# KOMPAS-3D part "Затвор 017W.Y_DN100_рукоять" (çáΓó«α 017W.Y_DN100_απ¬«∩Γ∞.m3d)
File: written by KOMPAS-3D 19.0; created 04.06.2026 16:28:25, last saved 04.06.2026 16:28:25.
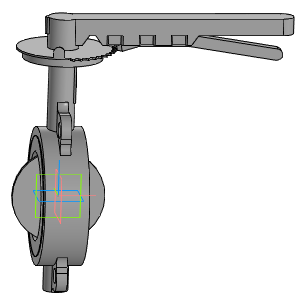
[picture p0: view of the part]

Document properties: Автор: Энергия; Полное имя файла: ..\..\..\3d для проектировщиков\017W разные\x.x Тип 017W.Y(S) Затвор дисковый поворотный межфланцевый\Затвор 017W.Y(S)_DN32-DN350_рукоять\Затвор 017W.Y_DN100_рукоять.a3d

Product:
- Part/product: Затвор 017W.Y_DN100_рукоять
    Масса: 14.9526

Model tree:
1. Операция без истории:1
